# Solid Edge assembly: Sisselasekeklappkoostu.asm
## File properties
Author: Türk
Template: Iso Assembly.asm
Last saved by: Türk
Revision: 2
Application: Solid Edge
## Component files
huklapp.par
Klapiavaja.par
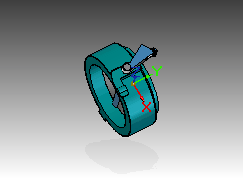
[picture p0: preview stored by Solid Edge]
